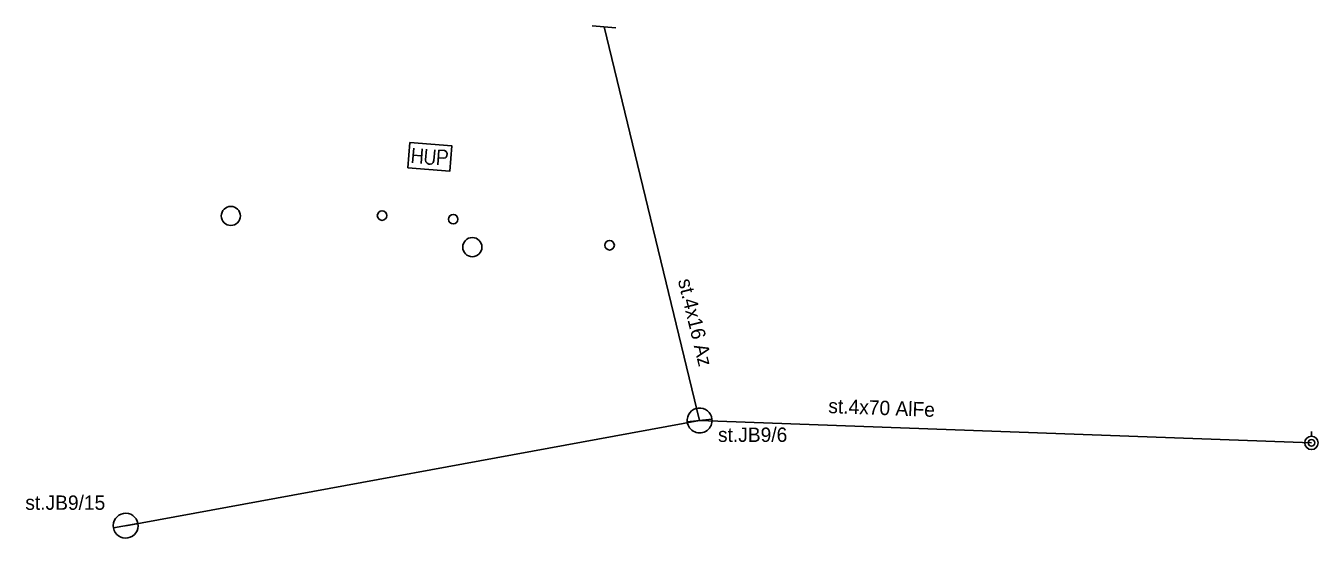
# Model space of a CAD drawing. Extents: x -762500 to -761250, y -1152983 to -1152297.
# Drawn here: x -761562.4 to -761494.8, y -1152533.5 to -1152506.8 of the extents above; entities that cross this region are included whole.
import ezdxf

# ---------------------------------------------------------------- set-up
doc = ezdxf.new("R2010")
doc.units = 0
for name, color, linetype in [('Vrstva 1', 7, 'Continuous'), ('Vrstva 2', 7, 'Continuous'), ('Vrstva 9', 7, 'Continuous')]:
    doc.layers.add(name, color=color, linetype=linetype)

msp = doc.modelspace()

# ---------------------------------------------------------------- linework, layer by layer
at = {"layer": 'Vrstva 1'}
for p, q in [((-761531.517, -1152506.875), (-761532.763, -1152506.765)), ((-761526.494, -1152527.318), (-761527.786, -1152527.462)), ((-761495.14, -1152528.21), (-761495.14, -1152527.96)), ((-761556.52, -1152532.774), (-761557.8, -1152533.006))]:
    msp.add_line(p, q, dxfattribs=at)
for points in [[(-761527.14, -1152527.39), (-761532.14, -1152506.82)], [(-761527.14, -1152527.39), (-761557.16, -1152532.89)], [(-761527.14, -1152527.39), (-761495.14, -1152528.56)]]:
    msp.add_lwpolyline(points, dxfattribs=at)
for radius in [0.35, 0.175]:
    msp.add_circle((-761495.14, -1152528.56), radius, dxfattribs=at)
for centre, start, end in [((-761527.14, -1152527.39), 6.39093, 186.39093), ((-761527.14, -1152527.39), 186.39093, 6.39093), ((-761557.16, -1152532.89), 10.26757, 190.26757), ((-761557.16, -1152532.89), 190.26757, 10.26757)]:
    msp.add_arc(centre, 0.65, start, end, dxfattribs=at)
at = {"layer": 'Vrstva 9'}
for points in [[(-761542.29, -1152512.865), (-761540.097, -1152513.043), (-761540.204, -1152514.359), (-761542.396, -1152514.181), (-761542.29, -1152512.865)], [(-761542.093, -1152513.157), (-761542.155, -1152513.925)], [(-761541.714, -1152513.961), (-761541.652, -1152513.193)], [(-761541.435, -1152513.211), (-761541.479, -1152513.761), (-761541.457, -1152513.871), (-761541.395, -1152513.949), (-761541.306, -1152513.994), (-761541.243, -1152513.999), (-761541.147, -1152513.969), (-761541.079, -1152513.902), (-761541.039, -1152513.797), (-761540.994, -1152513.246)], [(-761540.839, -1152514.031), (-761540.777, -1152513.264)], [(-761540.777, -1152513.264), (-761540.492, -1152513.287), (-761540.403, -1152513.331), (-761540.373, -1152513.37), (-761540.348, -1152513.444), (-761540.357, -1152513.554), (-761540.394, -1152513.624), (-761540.43, -1152513.656), (-761540.524, -1152513.686), (-761540.809, -1152513.663)], [(-761542.122, -1152513.519), (-761541.681, -1152513.555)]]:
    msp.add_lwpolyline(points, dxfattribs=at)
for centre, radius in [((-761551.66, -1152516.7), 0.5), ((-761543.75, -1152516.68), 0.25), ((-761540.03, -1152516.87), 0.25), ((-761539.03, -1152518.33), 0.5), ((-761531.85, -1152518.23), 0.25)]:
    msp.add_circle(centre, radius, dxfattribs=at)

# ---------------------------------------------------------------- texts
at = {"layer": 'Vrstva 2'}
for s, rotation, p in [('st.4x16 Az', 283.66207, (-761528.28, -1152520.07)), ('st.4x70 AlFe', 357.90606, (-761520.42, -1152527))]:
    msp.add_text(s, height=0.75, rotation=rotation, dxfattribs=at).set_placement(p)
for s, p in [('st.JB9/6', (-761526.18, -1152528.51)), ('st.JB9/15', (-761562.41, -1152532.06))]:
    msp.add_text(s, height=0.75, dxfattribs=at).set_placement(p)

doc.saveas('drawing.dxf')
